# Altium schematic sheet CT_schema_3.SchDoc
size 335 x 238 mm
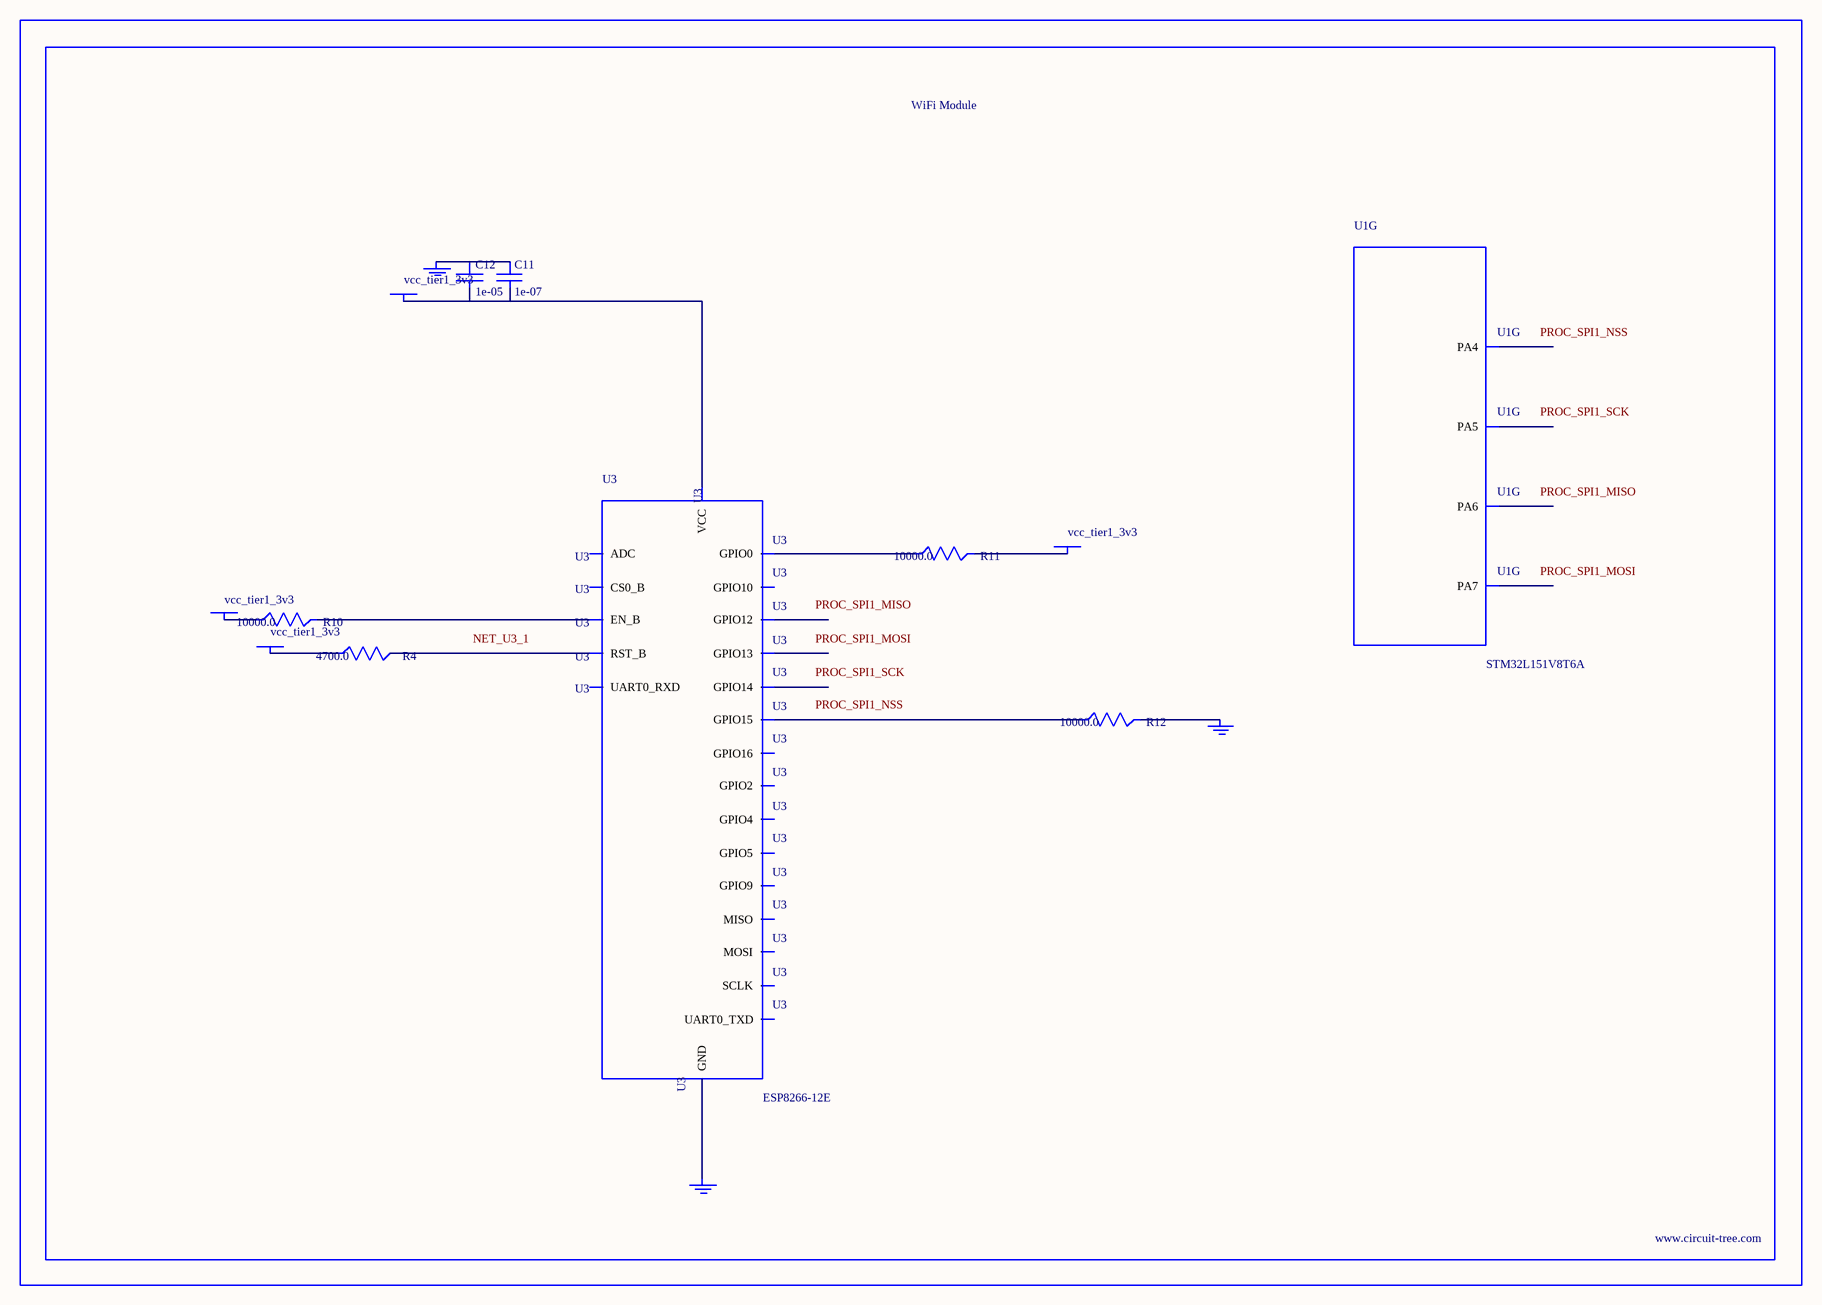
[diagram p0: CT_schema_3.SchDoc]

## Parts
BORDER2  (no value)
C11  1e-07  [C0402]
C12  1e-05  [C0805]
GND_INSTANCE_2_0  (no value)
GND_INSTANCE_2_1  (no value)
GND_INSTANCE_2_2  (no value)
POWER_INSTANCE_2_0  vcc_tier1_3v3
POWER_INSTANCE_2_1  vcc_tier1_3v3
POWER_INSTANCE_2_2  vcc_tier1_3v3
POWER_INSTANCE_2_3  vcc_tier1_3v3
R4  4700.0  [R0603]
R10  10000.0  [R0603]
R11  10000.0  [R0603]
R12  10000.0  [R0603]
U1  STM32L151V8T6A  [LQFP100]  (part G of 9)
U3  ESP8266-12E  [ESP8266-12E]

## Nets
NetC11_1: C11.1 C12.1 GND_INSTANCE_2_0.0(GND)
NetC11_2: C11.2 C12.2 POWER_INSTANCE_2_1.0(PWR) U3.8(VCC)
NetGND_INSTANCE_2_1_0: GND_INSTANCE_2_1.0(GND) R12.2
NetGND_INSTANCE_2_2_0: GND_INSTANCE_2_2.0(GND) U3.15(GND)
NetPOWER_INSTANCE_2_0_0: POWER_INSTANCE_2_0.0(PWR) R10.1
NetPOWER_INSTANCE_2_2_0: POWER_INSTANCE_2_2.0(PWR) R11.2
NetPOWER_INSTANCE_2_3_0: POWER_INSTANCE_2_3.0(PWR) R4.1
NetR4_2: R4.2 U3.1(RST_B)
NetR10_2: R10.2 U3.3(EN_B)
NetR11_1: R11.1 U3.18(GPIO0)
NetR12_1: R12.1 U3.16(GPIO15)

Not connected (* = marked no-connect by the designer): U1 29(PA4) 30(PA5) 31(PA6) 32(PA7); U3 2(ADC) 4(GPIO16) 5(GPIO14) 6(GPIO12) 7(GPIO13) 9(CS0_B) 10(MISO) 11(GPIO9) 12(GPIO10) 13(MOSI) 14(SCLK) 17(GPIO2) 19(GPIO4) 20(GPIO5) 21(UART0_RXD) 22(UART0_TXD)

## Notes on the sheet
- Labels drawn without touching a wire or pin: NET_U3_1, PROC_SPI1_MISO, PROC_SPI1_MOSI, PROC_SPI1_NSS, PROC_SPI1_SCK

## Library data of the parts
BORDER2 = BORDER_PAGE2
C11 = C0402C104K3RACTU
C12 = C0805C106K8RACTU
GND_INSTANCE_2_0-GND_INSTANCE_2_2 = GND
POWER_INSTANCE_2_0-POWER_INSTANCE_2_3 = PWR
R4 = RC0603JR-074K7L
R10-R12 = RC0603JR-0710KL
